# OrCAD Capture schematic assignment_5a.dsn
size A3
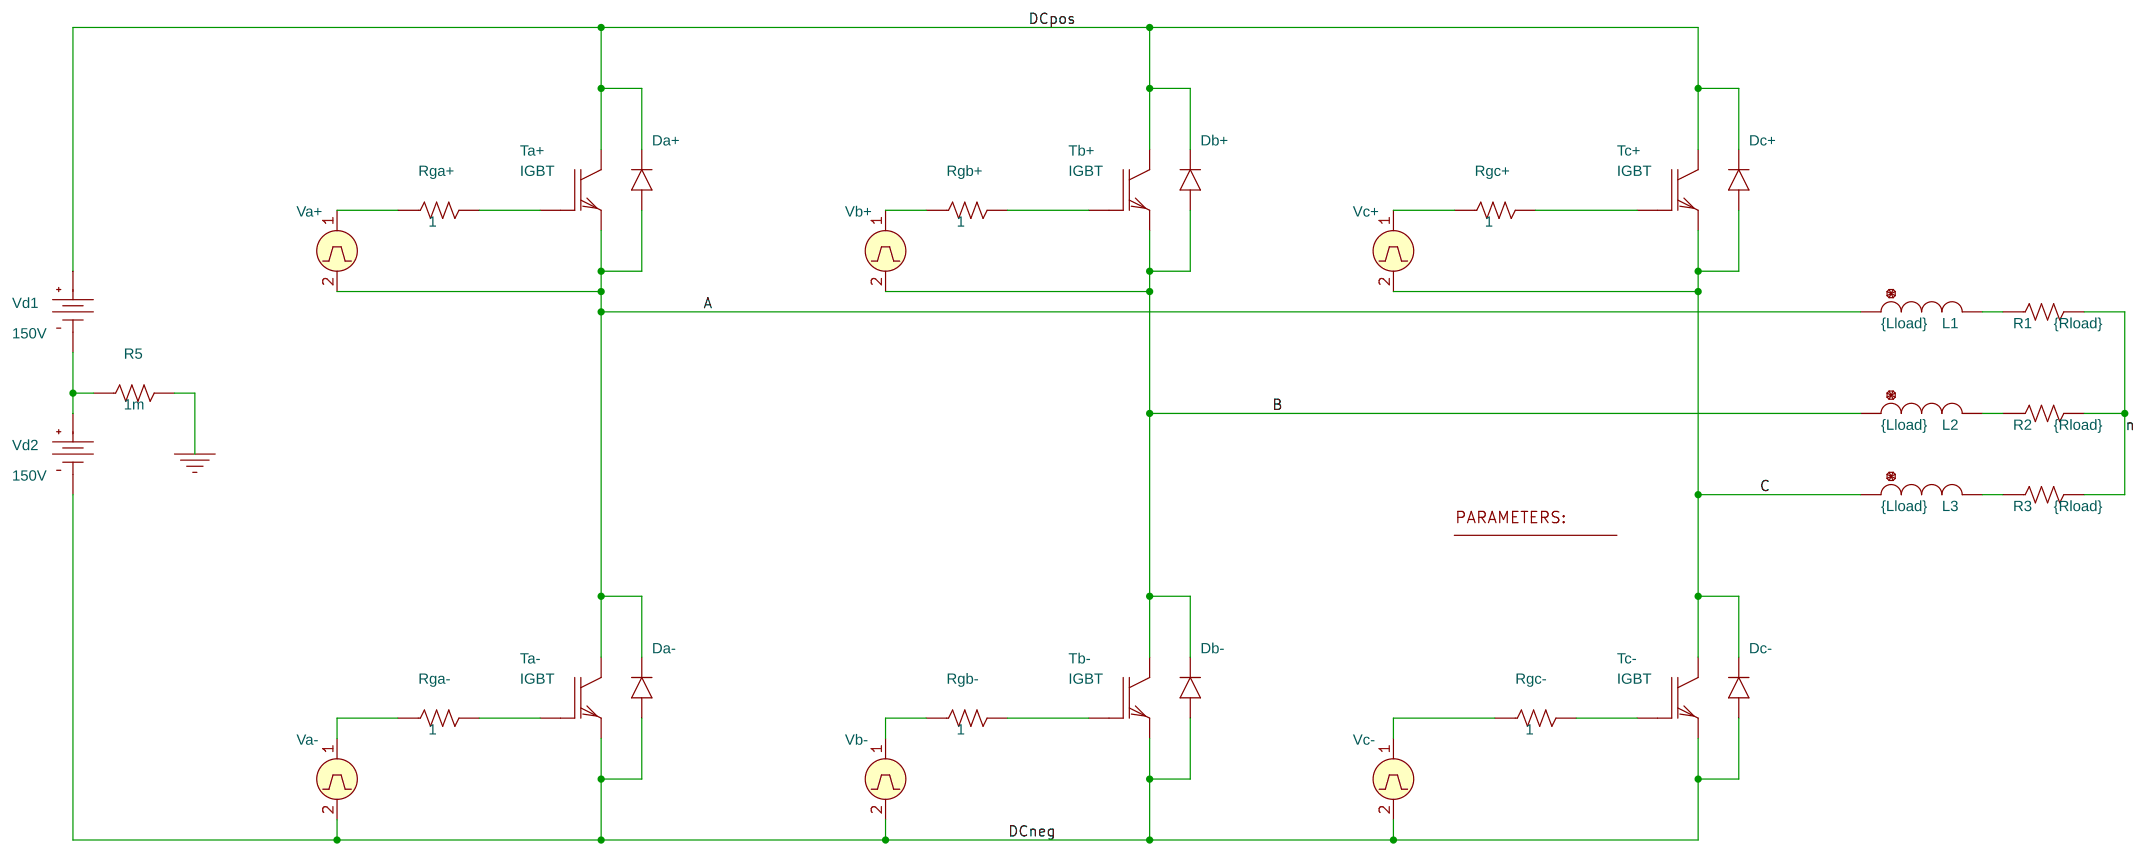
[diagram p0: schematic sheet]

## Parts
1  PARAM
Da+  d
Da-  d
Db+  d
Db-  d
Dc+  d
Dc-  d
L1  {Lload}  [DISC/.350x.175/LS.200x.100/.034]
L2  {Lload}  [DISC/.350x.175/LS.200x.100/.034]
L3  {Lload}  [DISC/.350x.175/LS.200x.100/.034]
R1  {Rload}  [AX/RC05]
R2  {Rload}  [AX/RC05]
R3  {Rload}  [AX/RC05]
R5  1m  [AX/RC05]
Rga+  1  [AX/RC05]
Rga-  1  [AX/RC05]
Rgb+  1  [AX/RC05]
Rgb-  1  [AX/RC05]
Rgc+  1  [AX/RC05]
Rgc-  1  [AX/RC05]
Ta+  IGBT
Ta-  IGBT
Tb+  IGBT
Tb-  IGBT
Tc+  IGBT
Tc-  IGBT
Va+  VPULSE
Va-  VPULSE
Vb+  VPULSE
Vb-  VPULSE
Vc+  VPULSE
Vc-  VPULSE
Vd1  VDC
Vd2  VDC

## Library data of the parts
1 = PARAM: Lload: 10u; freq: 50Hz
Da+ Da- Db+ Db- Dc+ Dc- = diode
L1 L2 = L: IC: -7A
L3 = L: IC: 14A
R1-R3 R5 Rga+ Rga- Rgb+ Rgb- Rgc+ Rgc- = R
Ta+ Ta- Tb+ Tb- Tc+ Tc- = CM300DY-24H
Va+ = VPULSE: PER: {1/freq}; PW: {0.5/freq}; TD: 200n; TF: 200n; TR: 200n; V1: 0; V2: 15
Va- = VPULSE: PER: {1/freq}; PW: {{0.5/freq}+400n}; TD: 0; TF: 200n; TR: 200n; V1: 15; V2: 0
Vb+ = VPULSE: PER: {1/freq}; PW: {0.5/freq}; TD: {1/(3*freq)+200n}; TF: 200n; TR: 200n; V1: 0; V2: 15
Vb- = VPULSE: PER: {1/freq}; PW: {{0.5/freq}+400n}; TD: {1/(3*freq)}; TF: 200n; TR: 200n; V1: 15; V2: 0
Vc+ = VPULSE: PER: {1/freq}; PW: {0.5/freq}; TD: {2/(3*freq)+200n}; TF: 200n; TR: 200n; V1: 0; V2: 15
Vc- = VPULSE: PER: {1/freq}; PW: {{0.5/freq}+400n}; TD: {2/(3*freq)}; TF: 200n; TR: 200n; V1: 15; V2: 0
Vd1 Vd2 = VDC: DC: 150V

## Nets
0: R5.2
A: Da+.1(A) Da-.2(K) L1.1 Ta+.3(E) Ta-.2(C) Va+.2(-)
B: Db+.1(A) Db-.2(K) L2.1 Tb+.3(E) Tb-.2(C) Vb+.2(-)
C: Dc+.1(A) Dc-.2(K) L3.1 Tc+.3(E) Tc-.2(C) Vc+.2(-)
DCneg: Da-.1(A) Db-.1(A) Dc-.1(A) Ta-.3(E) Tb-.3(E) Tc-.3(E) Va-.2(-) Vb-.2(-) Vc-.2(-) Vd2.1(-)
DCpos: Da+.2(K) Db+.2(K) Dc+.2(K) Ta+.2(C) Tb+.2(C) Tc+.2(C) Vd1.0(+)
n: R1.2 R2.2 R3.2
N10838: L1.2 R1.1
N16003: L2.2 R2.1
N29911: Rgc-.1 Vc-.1(+)
N30551: Rgc+.1 Vc+.1(+)
N31270: Rgb+.1 Vb+.1(+)
N31722: Rgb-.1 Vb-.1(+)
N32908: Rga+.1 Va+.1(+)
N34378: Rga-.1 Va-.1(+)
N48783: Rga-.2 Ta-.1(G)
N49021: Rga+.2 Ta+.1(G)
N49180: Rgb+.2 Tb+.1(G)
N49286: Rgc+.2 Tc+.1(G)
N49583: Rgb-.2 Tb-.1(G)
N49690: Rgc-.2 Tc-.1(G)
N52696: L3.2 R3.1
N61238: R5.1 Vd1.1(-) Vd2.0(+)
